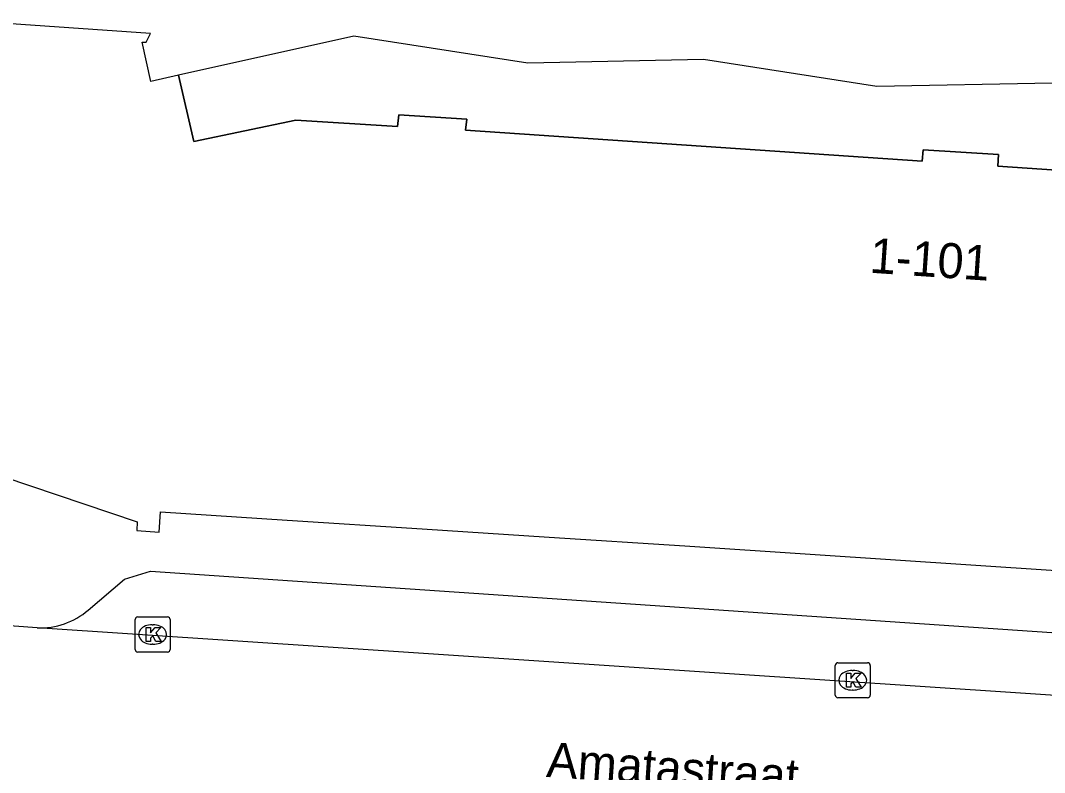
# Model space of a CAD drawing. Extents: x 161848 to 162726, y 385382 to 386521.
# Drawn here: x 161957.23 to 161986.5, y 385844.42 to 385865.9 of the extents above; entities that cross this region are included whole.
import ezdxf

# ---------------------------------------------------------------- set-up
doc = ezdxf.new("R2010")
doc.units = 0
for name, color, linetype in [('IMGEO_Kolk', 7, 'Continuous'), ('IMGEO_Openbare_ruimte_label', 7, 'Continuous'), ('IMGEO_Pand', 7, 'Continuous'), ('IMGEO_Pand_nummerreeks', 7, 'Continuous'), ('IMGEO_Pand_overbouw', 7, 'Continuous'), ('IMGEO_Rijbaan_lokaal_open', 7, 'Continuous'), ('IMGEO_Voetpad_open', 7, 'Continuous')]:
    doc.layers.add(name, color=color, linetype=linetype)

msp = doc.modelspace()

# ---------------------------------------------------------------- linework, layer by layer
at = {"layer": 'IMGEO_Kolk'}
for p, q in [((161960.585, 385848.862), (161961.437, 385848.862)), ((161960.51, 385847.936), (161960.51, 385848.788)), ((161960.998, 385848.642), (161961.023, 385848.642)), ((161961.511, 385848.788), (161961.511, 385847.936)), ((161961.021, 385848.082), (161960.996, 385848.082)), ((161961.437, 385847.862), (161960.585, 385847.862)), ((161980.516, 385846.629), (161980.516, 385847.481)), ((161980.591, 385847.555), (161981.443, 385847.555)), ((161981.517, 385847.481), (161981.517, 385846.629)), ((161981.004, 385847.335), (161981.029, 385847.335)), ((161981.443, 385846.555), (161980.591, 385846.555)), ((161981.027, 385846.775), (161981.002, 385846.775))]:
    msp.add_line(p, q, dxfattribs=at)
for points in [[(161960.585, 385848.862), (161961.437, 385848.862)], [(161960.51, 385847.936), (161960.51, 385848.788)], [(161960.831, 385848.562), (161960.954, 385848.562), (161960.954, 385848.411), (161961.084, 385848.562), (161961.248, 385848.562), (161961.102, 385848.411), (161961.255, 385848.162), (161961.103, 385848.162), (161961.018, 385848.326), (161960.954, 385848.259), (161960.954, 385848.162), (161960.831, 385848.162), (161960.831, 385848.562)], [(161961.511, 385848.788), (161961.511, 385847.936)], [(161961.437, 385847.862), (161960.585, 385847.862)], [(161980.516, 385846.629), (161980.516, 385847.481)], [(161980.591, 385847.555), (161981.443, 385847.555)], [(161981.517, 385847.481), (161981.517, 385846.629)], [(161980.837, 385847.255), (161980.96, 385847.255), (161980.96, 385847.104), (161981.09, 385847.255), (161981.254, 385847.255), (161981.108, 385847.104), (161981.261, 385846.855), (161981.109, 385846.855), (161981.024, 385847.019), (161980.96, 385846.952), (161980.96, 385846.855), (161980.837, 385846.855), (161980.837, 385847.255)], [(161981.443, 385846.555), (161980.591, 385846.555)]]:
    msp.add_lwpolyline(points, dxfattribs=at)
for centre, start, end in [((161960.587, 385848.786), 91.552, 178.448), ((161960.587, 385848.786), 91.552, 178.448), ((161961.435, 385848.786), 1.552, 88.448), ((161961.435, 385848.786), 1.552, 88.448), ((161960.587, 385847.938), 181.552, 268.448), ((161960.587, 385847.938), 181.552, 268.448), ((161961.435, 385847.938), 271.552, 358.448), ((161961.435, 385847.938), 271.552, 358.448), ((161980.593, 385847.479), 91.552, 178.448), ((161980.593, 385847.479), 91.552, 178.448), ((161981.441, 385847.479), 1.552, 88.448), ((161981.441, 385847.479), 1.552, 88.448), ((161980.593, 385846.631), 181.552, 268.448), ((161980.593, 385846.631), 181.552, 268.448), ((161981.441, 385846.631), 271.552, 358.448), ((161981.441, 385846.631), 271.552, 358.448)]:
    msp.add_arc(centre, 0.0765, start, end, dxfattribs=at)
for centre, major_axis, ratio, start_param, end_param in [((161960.997, 385848.362), (-0.387, 0.002), 0.722429, 4.712389, 7.853982), ((161961.022, 385848.362), (-0.39, 0.002), 0.717154, 1.570796, 4.712389), ((161981.003, 385847.055), (-0.387, 0.002), 0.722429, 4.712389, 7.853982), ((161981.028, 385847.055), (-0.39, 0.002), 0.717154, 1.570796, 4.712389)]:
    msp.add_ellipse(centre, major_axis=major_axis, ratio=ratio, start_param=start_param, end_param=end_param, dxfattribs=at)
at = {"layer": 'IMGEO_Pand'}
for points in [[(161998.165, 385860.852), (161985.16, 385861.737), (161985.183, 385862.071), (161983.031, 385862.212), (161982.999, 385861.883), (161969.947, 385862.767), (161969.985, 385863.086), (161968.049, 385863.21), (161968.007, 385862.871), (161965.1, 385863.054), (161962.186, 385862.443), (161961.754, 385864.345), (161960.962, 385864.157), (161960.714, 385865.281), (161960.826, 385865.284), (161960.951, 385865.53), (161955.589, 385865.903)], [(161956.755, 385852.867), (161960.57, 385851.585), (161960.558, 385851.332), (161961.2, 385851.29), (161961.233, 385851.863), (161964.857, 385851.632), (161968.718, 385851.38), (161972.339, 385851.144), (161976.22, 385850.891), (161979.796, 385850.658), (161986.827, 385850.19), (161990.402, 385849.952), (161994.307, 385849.692), (161997.884, 385849.454), (162000, 385849.31), (162001.8, 385849.188), (162005.373, 385848.946), (162009.272, 385848.691), (162012.694, 385848.468)]]:
    msp.add_lwpolyline(points, dxfattribs=at)
at = {"layer": 'IMGEO_Pand_overbouw'}
msp.add_lwpolyline([(161986.722, 385864.115), (161981.71, 385864.014), (161976.752, 385864.788), (161971.735, 385864.681), (161966.762, 385865.454), (161961.754, 385864.345), (161962.186, 385862.443), (161965.1, 385863.054), (161968.007, 385862.871), (161968.049, 385863.21), (161969.985, 385863.086), (161969.947, 385862.767), (161982.999, 385861.883), (161983.031, 385862.212), (161985.183, 385862.071), (161985.16, 385861.737), (161998.165, 385860.852)], dxfattribs=at)
at = {"layer": 'IMGEO_Rijbaan_lokaal_open'}
for points in [[(161957.713, 385848.555), (161949.439, 385849.157)], [(162012.207, 385844.929), (162000, 385845.743), (161957.713, 385848.555)]]:
    msp.add_lwpolyline(points, dxfattribs=at)
at = {"layer": 'IMGEO_Voetpad_open'}
msp.add_lwpolyline([(161959.169, 385849.06), (161960.209, 385849.941), (161960.952, 385850.174), (162000, 385847.511), (162007.724, 385846.922), (162011.566, 385846.591)], dxfattribs=at)
msp.add_arc((161957.801, 385850.652), 2.099, 267.5871, 310.6701, dxfattribs=at)

# ---------------------------------------------------------------- texts
at = {"layer": 'IMGEO_Openbare_ruimte_label'}
msp.add_text('Amatastraat', height=1, rotation=356.1593, dxfattribs=at).set_placement((161972.244, 385844.294))
at = {"layer": 'IMGEO_Pand_nummerreeks'}
msp.add_text('1-101', height=1, rotation=356.1325, dxfattribs=at).set_placement((161981.483, 385858.699))

doc.saveas('drawing.dxf')
